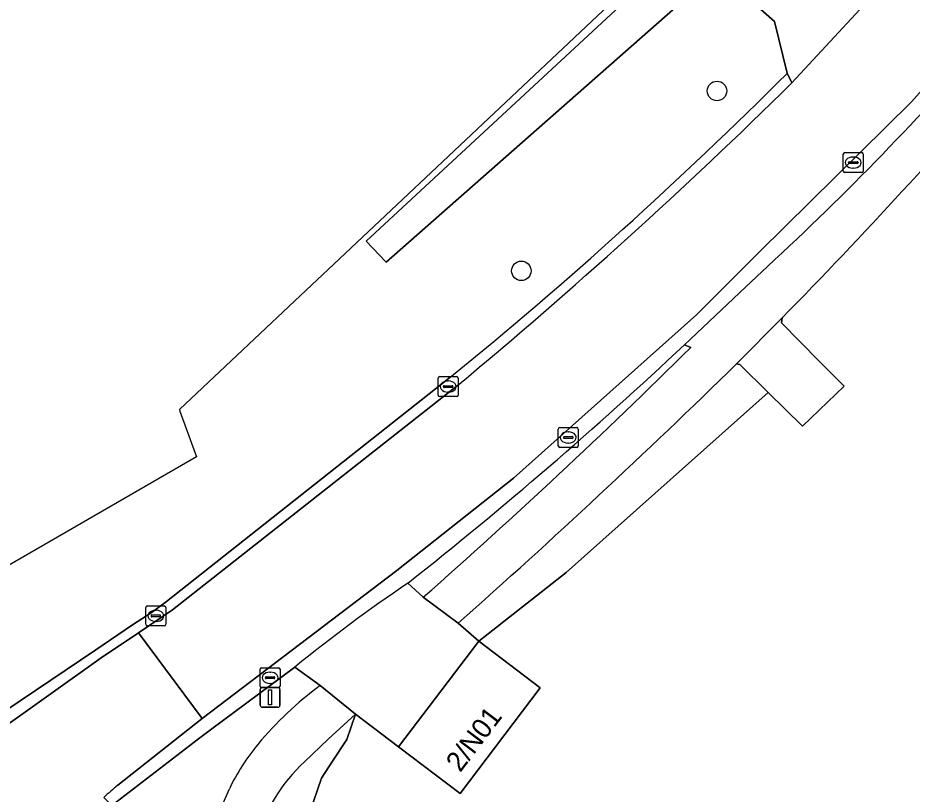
# Model space of a CAD drawing. Extents: x 152881 to 155736, y 382924 to 386919.
# Drawn here: x 152912.31 to 152957.26, y 384950.16 to 384989.18 of the extents above; entities that cross this region are included whole.
import ezdxf

# ---------------------------------------------------------------- set-up
doc = ezdxf.new("R2010")
doc.units = 0
for name, color, linetype in [('IMGEO_Boom', 7, 'Continuous'), ('IMGEO_Erf', 7, 'Continuous'), ('IMGEO_Fietspad_gesloten', 7, 'Continuous'), ('IMGEO_Groenvoorziening', 7, 'Continuous'), ('IMGEO_Kolk', 7, 'Continuous'), ('IMGEO_Pand', 7, 'Continuous'), ('IMGEO_Pand_nummerreeks', 7, 'Continuous'), ('IMGEO_Rijbaan_lokaal_gesloten', 7, 'Continuous'), ('IMGEO_Rijbaan_lokaal_open', 7, 'Continuous'), ('IMGEO_Verkeersbordpaal', 7, 'Continuous'), ('IMGEO_Waterloop', 7, 'Continuous')]:
    doc.layers.add(name, color=color, linetype=linetype)

msp = doc.modelspace()

# ---------------------------------------------------------------- linework, layer by layer
at = {"layer": 'IMGEO_Boom'}
for centre in [(152947.452, 384985.506), (152937.617, 384976.464)]:
    msp.add_circle(centre, 0.489, dxfattribs=at)
at = {"layer": 'IMGEO_Erf'}
msp.add_lwpolyline([(152927.084, 384975.763), (152920.433, 384969.493), (152927.085, 384975.764)], close=True, dxfattribs=at)
msp.add_lwpolyline([(152950.725, 384974.104), (152950.689, 384973.85), (152952.592, 384971.926), (152953.835, 384970.67), (152951.749, 384968.654), (152950.028, 384970.351), (152946.934, 384967.593), (152939.863, 384961.291), (152935.478, 384957.851), (152938.57, 384955.499), (152934.539, 384950.19), (152931.439, 384952.54), (152929.279, 384954.181), (152928.844, 384952.903), (152928.128, 384951.81), (152927.569, 384950.958), (152926.4, 384947.544)], dxfattribs=at)
msp.add_arc((152770.156, 385151.69), 253.263, 315.47725, 319.44526, dxfattribs=at)
at = {"layer": 'IMGEO_Fietspad_gesloten'}
for points in [[(152949.991, 384976.683), (152948.903, 384975.656), (152945.824, 384972.748), (152946.132, 384972.615)], [(152948.432, 384971.782), (152950.725, 384974.104)], [(152932.686, 384960.056), (152934.439, 384958.75)], [(152926.712, 384951.78), (152927.904, 384952.921), (152929.279, 384954.181), (152927.508, 384955.614)]]:
    msp.add_lwpolyline(points, dxfattribs=at)
for centre, radius, start, end in [((152849.838, 385085.062), 147.569, 312.74109, 319.00316), ((152770.156, 385151.69), 253.263, 315.47725, 319.44526), ((152727.377, 385193.342), 310.764, 311.3501, 314.74283), ((152680.181, 385245.786), 383.454, 311.53471, 314.39217), ((152937.864, 384941.495), 17.51, 126.2593, 140.3924), ((152932.832, 384945.65), 10.984, 140.3545, 154.2191), ((152932.805, 384945.263), 8.921, 133.0732, 163.003), ((152908.639, 384955.958), 15.335, 311.661, 338.8562)]:
    msp.add_arc(centre, radius, start, end, dxfattribs=at)
at = {"layer": 'IMGEO_Groenvoorziening'}
for points in [[(152950.985, 384986.404), (152950.337, 384988.994), (152946.282, 384992.575), (152945.603, 384993.175), (152945.693, 384993.638), (152943.451, 384991.193)], [(152943.451, 384991.193), (152927.62, 384976.268), (152927.085, 384975.764), (152920.433, 384969.493), (152920.46, 384969.417), (152921.287, 384967.115), (152912.167, 384961.843), (152908.6, 384959.773), (152907.793, 384959.669), (152906.478, 384958.657), (152903.663, 384959.312), (152899.417, 384953.516), (152899.873, 384953.949), (152900.494, 384953.465), (152900.84, 384954.217)], [(152946.132, 384972.615), (152945.824, 384972.748)], [(152934.439, 384958.75), (152935.478, 384957.851), (152939.863, 384961.291), (152946.934, 384967.593), (152950.028, 384970.351), (152948.603, 384971.756), (152948.432, 384971.782)], [(152910.53, 384954.589), (152910.924, 384953.841), (152916.225, 384957.419), (152918.078, 384958.671), (152919.016, 384959.272), (152919.782, 384959.841), (152934.028, 384971.097)], [(152931.914, 384960.767), (152932.686, 384960.056)], [(152927.508, 384955.614), (152926.228, 384956.548), (152921.994, 384953.396), (152921.384, 384952.942), (152917.038, 384949.591), (152917.573, 384949.062)], [(152927.593, 384940.822), (152927.3, 384941.255), (152926.902, 384941.969), (152926.581, 384942.721), (152926.34, 384943.502), (152926.182, 384944.304), (152926.108, 384945.118), (152926.121, 384945.935), (152926.218, 384946.747), (152926.4, 384947.544), (152927.569, 384950.958), (152928.128, 384951.81), (152928.844, 384952.903), (152929.279, 384954.181), (152927.904, 384952.921), (152926.712, 384951.78)]]:
    msp.add_lwpolyline(points, dxfattribs=at)
for points in [[(152929.812, 384977.958), (152943.943, 384991.066), (152944.477, 384990.455), (152945.233, 384989.589), (152930.815, 384976.892)], [(152927.62, 384976.268), (152927.084, 384975.763), (152927.085, 384975.764)]]:
    msp.add_lwpolyline(points, close=True, dxfattribs=at)
for centre, radius, start, end in [((152792.046, 385145.43), 224.836, 309.16045, 314.98437), ((152795.031, 385133.754), 220.594, 308.35422, 313.12392), ((152727.377, 385193.342), 310.764, 311.3501, 314.74283), ((152680.181, 385245.786), 383.454, 311.53471, 314.39217), ((152937.864, 384941.495), 17.51, 126.2593, 140.3924), ((152932.832, 384945.65), 10.984, 140.3545, 154.2191), ((152932.805, 384945.263), 8.921, 133.0732, 163.003), ((152908.639, 384955.958), 15.335, 311.661, 338.8562)]:
    msp.add_arc(centre, radius, start, end, dxfattribs=at)
at = {"layer": 'IMGEO_Kolk'}
for p, q in [((152953.871, 384982.405), (152954.723, 384982.405)), ((152953.796, 384981.479), (152953.796, 384982.331)), ((152954.098, 384981.948), (152954.496, 384981.948)), ((152954.284, 384982.185), (152954.309, 384982.185)), ((152954.797, 384982.331), (152954.797, 384981.479)), ((152954.055, 384981.899), (152954.055, 384981.911)), ((152954.493, 384981.862), (152954.095, 384981.862)), ((152954.307, 384981.625), (152954.282, 384981.625)), ((152954.539, 384981.911), (152954.539, 384981.899)), ((152954.723, 384981.405), (152953.871, 384981.405)), ((152933.438, 384970.22), (152933.438, 384971.072)), ((152933.513, 384971.146), (152934.365, 384971.146)), ((152933.926, 384970.926), (152933.951, 384970.926)), ((152934.439, 384971.072), (152934.439, 384970.22)), ((152933.697, 384970.64), (152933.697, 384970.652)), ((152934.135, 384970.603), (152933.737, 384970.603)), ((152933.74, 384970.689), (152934.138, 384970.689)), ((152933.949, 384970.366), (152933.924, 384970.366)), ((152934.181, 384970.652), (152934.181, 384970.64)), ((152934.365, 384970.146), (152933.513, 384970.146)), ((152939.475, 384967.66), (152939.475, 384968.512)), ((152939.55, 384968.586), (152940.402, 384968.586)), ((152940.476, 384968.512), (152940.476, 384967.66)), ((152939.734, 384968.08), (152939.734, 384968.092)), ((152940.172, 384968.043), (152939.774, 384968.043)), ((152939.777, 384968.129), (152940.175, 384968.129)), ((152939.963, 384968.366), (152939.988, 384968.366)), ((152940.218, 384968.092), (152940.218, 384968.08)), ((152940.402, 384967.586), (152939.55, 384967.586)), ((152939.986, 384967.806), (152939.961, 384967.806)), ((152918.744, 384958.694), (152918.744, 384959.546)), ((152918.819, 384959.62), (152919.671, 384959.62)), ((152919.745, 384959.546), (152919.745, 384958.694)), ((152919.003, 384959.114), (152919.003, 384959.126)), ((152919.441, 384959.077), (152919.043, 384959.077)), ((152919.046, 384959.163), (152919.444, 384959.163)), ((152919.232, 384959.4), (152919.257, 384959.4)), ((152919.487, 384959.126), (152919.487, 384959.114)), ((152919.671, 384958.62), (152918.819, 384958.62)), ((152919.255, 384958.84), (152919.23, 384958.84)), ((152924.488, 384955.58), (152924.488, 384956.432)), ((152924.563, 384956.506), (152925.415, 384956.506)), ((152925.489, 384956.432), (152925.489, 384955.58)), ((152924.747, 384956), (152924.747, 384956.012)), ((152925.185, 384955.963), (152924.787, 384955.963)), ((152924.79, 384956.049), (152925.188, 384956.049)), ((152924.976, 384956.286), (152925.001, 384956.286)), ((152925.231, 384956.012), (152925.231, 384956)), ((152925.415, 384955.506), (152924.563, 384955.506)), ((152924.999, 384955.726), (152924.974, 384955.726))]:
    msp.add_line(p, q, dxfattribs=at)
for points in [[(152953.871, 384982.405), (152954.723, 384982.405)], [(152953.796, 384981.479), (152953.796, 384982.331)], [(152954.797, 384982.331), (152954.797, 384981.479)], [(152954.723, 384981.405), (152953.871, 384981.405)], [(152933.438, 384970.22), (152933.438, 384971.072)], [(152933.513, 384971.146), (152934.365, 384971.146)], [(152934.439, 384971.072), (152934.439, 384970.22)], [(152934.365, 384970.146), (152933.513, 384970.146)], [(152939.475, 384967.66), (152939.475, 384968.512)], [(152939.55, 384968.586), (152940.402, 384968.586)], [(152940.476, 384968.512), (152940.476, 384967.66)], [(152940.402, 384967.586), (152939.55, 384967.586)], [(152918.744, 384958.694), (152918.744, 384959.546)], [(152918.819, 384959.62), (152919.671, 384959.62)], [(152919.745, 384959.546), (152919.745, 384958.694)], [(152919.671, 384958.62), (152918.819, 384958.62)], [(152924.488, 384955.58), (152924.488, 384956.432)], [(152924.563, 384956.506), (152925.415, 384956.506)], [(152925.489, 384956.432), (152925.489, 384955.58)], [(152925.415, 384955.506), (152924.563, 384955.506)]]:
    msp.add_lwpolyline(points, dxfattribs=at)
for centre, radius, start, end in [((152953.873, 384982.329), 0.0765, 91.552, 178.448), ((152953.873, 384982.329), 0.0765, 91.552, 178.448), ((152954.721, 384982.329), 0.0765, 1.552, 88.448), ((152954.721, 384982.329), 0.0765, 1.552, 88.448), ((152954.095, 384981.908), 0.0403, 85.8775, 175.7526), ((152954.5, 384981.91), 0.0386, 1.7309, 96.639), ((152954.092, 384981.898), 0.0366, 178.938, 274.7102), ((152954.496, 384981.905), 0.043, 264.8664, 352.4533), ((152953.873, 384981.481), 0.0765, 181.552, 268.448), ((152953.873, 384981.481), 0.0765, 181.552, 268.448), ((152954.721, 384981.481), 0.0765, 271.552, 358.448), ((152954.721, 384981.481), 0.0765, 271.552, 358.448), ((152933.515, 384971.07), 0.0765, 91.552, 178.448), ((152933.515, 384971.07), 0.0765, 91.552, 178.448), ((152934.363, 384971.07), 0.0765, 1.552, 88.448), ((152934.363, 384971.07), 0.0765, 1.552, 88.448), ((152933.737, 384970.649), 0.0403, 85.8775, 175.7526), ((152933.734, 384970.639), 0.0366, 178.938, 274.7102), ((152934.138, 384970.646), 0.043, 264.8664, 352.4533), ((152934.142, 384970.651), 0.0386, 1.7309, 96.639), ((152933.515, 384970.222), 0.0765, 181.552, 268.448), ((152933.515, 384970.222), 0.0765, 181.552, 268.448), ((152934.363, 384970.222), 0.0765, 271.552, 358.448), ((152934.363, 384970.222), 0.0765, 271.552, 358.448), ((152939.552, 384968.51), 0.0765, 91.552, 178.448), ((152939.552, 384968.51), 0.0765, 91.552, 178.448), ((152940.4, 384968.51), 0.0765, 1.552, 88.448), ((152940.4, 384968.51), 0.0765, 1.552, 88.448), ((152939.774, 384968.089), 0.0403, 85.8775, 175.7526), ((152939.771, 384968.079), 0.0366, 178.938, 274.7102), ((152940.175, 384968.086), 0.043, 264.8664, 352.4533), ((152940.179, 384968.091), 0.0386, 1.7309, 96.639), ((152939.552, 384967.662), 0.0765, 181.552, 268.448), ((152939.552, 384967.662), 0.0765, 181.552, 268.448), ((152940.4, 384967.662), 0.0765, 271.552, 358.448), ((152940.4, 384967.662), 0.0765, 271.552, 358.448), ((152918.821, 384959.544), 0.0765, 91.552, 178.448), ((152918.821, 384959.544), 0.0765, 91.552, 178.448), ((152919.669, 384959.544), 0.0765, 1.552, 88.448), ((152919.669, 384959.544), 0.0765, 1.552, 88.448), ((152919.043, 384959.123), 0.0403, 85.8775, 175.7526), ((152919.04, 384959.113), 0.0366, 178.938, 274.7102), ((152919.444, 384959.12), 0.043, 264.8664, 352.4533), ((152919.448, 384959.125), 0.0386, 1.7309, 96.639), ((152918.821, 384958.696), 0.0765, 181.552, 268.448), ((152918.821, 384958.696), 0.0765, 181.552, 268.448), ((152919.669, 384958.696), 0.0765, 271.552, 358.448), ((152919.669, 384958.696), 0.0765, 271.552, 358.448), ((152924.565, 384956.43), 0.0765, 91.552, 178.448), ((152924.565, 384956.43), 0.0765, 91.552, 178.448), ((152925.413, 384956.43), 0.0765, 1.552, 88.448), ((152925.413, 384956.43), 0.0765, 1.552, 88.448), ((152924.787, 384956.009), 0.0403, 85.8775, 175.7526), ((152924.784, 384955.999), 0.0366, 178.938, 274.7102), ((152925.188, 384956.006), 0.043, 264.8664, 352.4533), ((152925.192, 384956.011), 0.0386, 1.7309, 96.639), ((152924.565, 384955.582), 0.0765, 181.552, 268.448), ((152924.565, 384955.582), 0.0765, 181.552, 268.448), ((152925.413, 384955.582), 0.0765, 271.552, 358.448), ((152925.413, 384955.582), 0.0765, 271.552, 358.448)]:
    msp.add_arc(centre, radius, start, end, dxfattribs=at)
for centre, major_axis, ratio, start_param, end_param in [((152954.283, 384981.905), (-0.387, 0.002), 0.722429, 4.712389, 7.853982), ((152954.308, 384981.905), (-0.39, 0.002), 0.717154, 1.570796, 4.712389), ((152933.925, 384970.646), (-0.387, 0.002), 0.722429, 4.712389, 7.853982), ((152933.95, 384970.646), (-0.39, 0.002), 0.717154, 1.570796, 4.712389), ((152939.962, 384968.086), (-0.387, 0.002), 0.722429, 4.712389, 7.853982), ((152939.987, 384968.086), (-0.39, 0.002), 0.717154, 1.570796, 4.712389), ((152919.231, 384959.12), (-0.387, 0.002), 0.722429, 4.712389, 7.853982), ((152919.256, 384959.12), (-0.39, 0.002), 0.717154, 1.570796, 4.712389), ((152924.975, 384956.006), (-0.387, 0.002), 0.722429, 4.712389, 7.853982), ((152925, 384956.006), (-0.39, 0.002), 0.717154, 1.570796, 4.712389)]:
    msp.add_ellipse(centre, major_axis=major_axis, ratio=ratio, start_param=start_param, end_param=end_param, dxfattribs=at)
at = {"layer": 'IMGEO_Pand'}
msp.add_lwpolyline([(152931.439, 384952.54), (152934.539, 384950.19), (152938.57, 384955.499), (152935.478, 384957.851)], close=True, dxfattribs=at)
at = {"layer": 'IMGEO_Rijbaan_lokaal_gesloten'}
for points in [[(152934.413, 384970.705), (152920.087, 384959.424), (152918.374, 384958.267), (152921.577, 384953.958), (152931.359, 384961.408), (152937.222, 384966.042), (152946.43, 384974.266), (152949.587, 384977.419), (152957.232, 384984.967), (152960.992, 384989.193), (152967.34, 384996.77), (152976.729, 385009.189), (152985.588, 385021.361), (152985.658, 385021.458), (152987.933, 385024.584), (152991.207, 385029.157), (153005.301, 385048.581), (153023.094, 385073.275)], [(152962.476, 384998.501), (152960.294, 384996.073), (152958.204, 384993.613), (152956.56, 384991.699), (152951.215, 384985.911)], [(152951.215, 384985.911), (152950.985, 384986.404)], [(152909.594, 384952.411), (152911.22, 384953.262), (152916.505, 384957.005), (152918.374, 384958.267), (152920.087, 384959.424), (152934.413, 384970.705)], [(152934.028, 384971.097), (152919.782, 384959.841), (152919.016, 384959.272), (152918.078, 384958.671), (152916.225, 384957.419), (152910.924, 384953.841)], [(152917.332, 384950.608), (152921.577, 384953.958), (152918.374, 384958.267), (152916.505, 384957.005), (152911.22, 384953.262), (152909.594, 384952.411)]]:
    msp.add_lwpolyline(points, dxfattribs=at)
for centre, radius, start, end in [((152792.046, 385145.43), 224.836, 309.16045, 314.98437), ((152765.646, 385174.071), 264.272, 309.68816, 314.60274), ((152765.646, 385174.071), 264.272, 309.68816, 314.60274), ((152925.13, 384941.139), 12.266, 129.4729, 133.8248)]:
    msp.add_arc(centre, radius, start, end, dxfattribs=at)
at = {"layer": 'IMGEO_Rijbaan_lokaal_open'}
for points in [[(152961.215, 384988.254), (152964.984, 384992.697), (152968.595, 384997.09), (152970.886, 385000), (152975.013, 385005.472), (152981.333, 385014.199), (152983.553, 385017.266), (152986.274, 385021.023), (152986.067, 385021.169), (152986.05, 385021.181), (152985.658, 385021.458), (152985.588, 385021.361), (152976.729, 385009.189), (152967.34, 384996.77), (152960.992, 384989.193), (152957.232, 384984.967), (152949.587, 384977.419), (152946.43, 384974.266), (152937.222, 384966.042), (152931.359, 384961.408), (152921.577, 384953.958), (152917.332, 384950.608)], [(152945.824, 384972.748), (152948.903, 384975.656), (152949.991, 384976.683)], [(152935.478, 384957.851), (152934.439, 384958.75), (152932.686, 384960.056), (152931.914, 384960.767)], [(152926.228, 384956.548), (152927.508, 384955.614), (152929.279, 384954.181), (152931.439, 384952.54), (152935.478, 384957.851)], [(152916.636, 384949.989), (152917.038, 384949.591), (152921.384, 384952.942), (152921.994, 384953.396), (152926.228, 384956.548)]]:
    msp.add_lwpolyline(points, dxfattribs=at)
for points in [[(152949.77, 384996.78), (152949.201, 384997.134), (152948.615, 384996.418), (152945.603, 384993.175), (152946.282, 384992.575), (152950.337, 384988.994), (152950.985, 384986.404), (152951.215, 384985.911), (152956.56, 384991.699), (152956.443, 384991.794), (152956.275, 384991.932), (152956.007, 384992.151)], [(152950.689, 384973.85), (152950.725, 384974.104), (152948.432, 384971.782), (152948.603, 384971.756), (152950.028, 384970.351), (152951.749, 384968.654), (152953.835, 384970.67), (152952.592, 384971.926)]]:
    msp.add_lwpolyline(points, close=True, dxfattribs=at)
for centre, radius, start, end in [((152849.838, 385085.062), 147.569, 312.74109, 319.00316), ((152795.031, 385133.754), 220.594, 308.35422, 313.12392), ((152980.061, 384889.938), 85.644, 124.2063, 128.94437), ((152980.061, 384889.938), 85.644, 124.2063, 128.94437), ((152925.13, 384941.139), 12.266, 129.4729, 133.8248)]:
    msp.add_arc(centre, radius, start, end, dxfattribs=at)
at = {"layer": 'IMGEO_Verkeersbordpaal'}
for p, q in [((152924.495, 384954.626), (152924.495, 384955.426)), ((152924.495, 384955.426), (152924.495, 384954.626)), ((152924.595, 384955.526), (152925.385, 384955.526)), ((152925.385, 384955.526), (152924.595, 384955.526)), ((152925.485, 384955.426), (152925.485, 384954.626)), ((152925.485, 384954.626), (152925.485, 384955.426)), ((152925.385, 384954.526), (152924.595, 384954.526)), ((152924.595, 384954.526), (152925.385, 384954.526))]:
    msp.add_line(p, q, dxfattribs=at)
msp.add_lwpolyline([(152924.915, 384955.401), (152925.065, 384955.401), (152925.065, 384954.651), (152924.915, 384954.651), (152924.915, 384955.401)], dxfattribs=at)
for centre, start, end in [((152924.595, 384955.426), 90, 180), ((152924.595, 384955.426), 90, 180), ((152925.385, 384955.426), 0, 90), ((152925.385, 384955.426), 360, 90), ((152924.595, 384954.626), 180, 270), ((152924.595, 384954.626), 180, 270), ((152925.385, 384954.626), 270, 0), ((152925.385, 384954.626), 270, 0)]:
    msp.add_arc(centre, 0.1, start, end, dxfattribs=at)
at = {"layer": 'IMGEO_Waterloop'}
msp.add_lwpolyline([(152929.812, 384977.958), (152930.815, 384976.892), (152945.233, 384989.589), (152944.477, 384990.455), (152943.943, 384991.066)], close=True, dxfattribs=at)

# ---------------------------------------------------------------- texts
at = {"layer": 'IMGEO_Pand_nummerreeks'}
msp.add_text('2/N01', height=1, rotation=52.858, dxfattribs=at).set_placement((152934.543, 384951.212))

doc.saveas('drawing.dxf')
